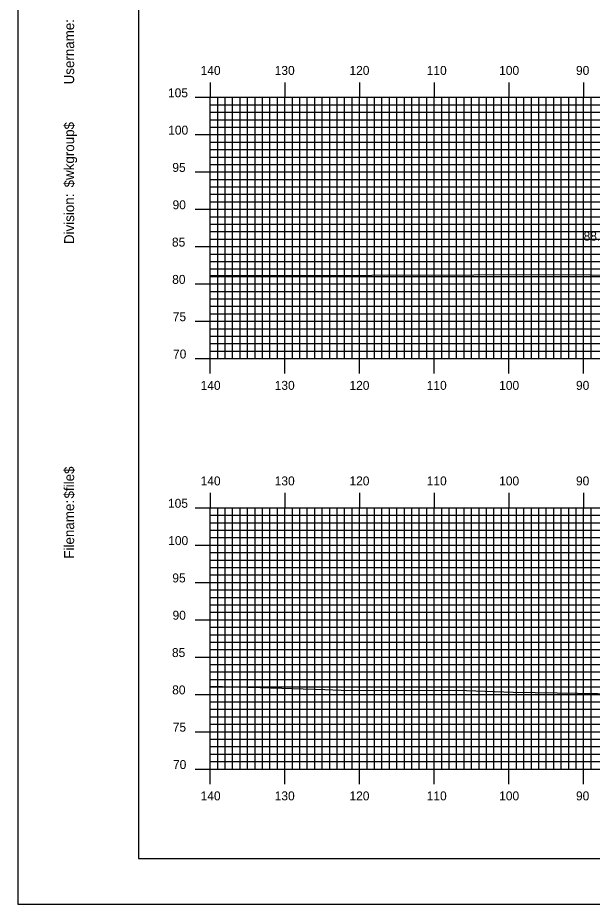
# Model space of a CAD drawing. Extents: x 1756675 to 1757019, y 442591 to 442811.
# Drawn here: x 1756675.3 to 1756752.2, y 442590.5 to 442709.3 of the extents above; entities that cross this region are included whole.
import ezdxf

# ---------------------------------------------------------------- set-up
doc = ezdxf.new("R2010")
doc.units = 0
for name, color, linetype in [('BORDER', 7, 'Continuous'), ('D_Text_Standard', 7, 'Continuous'), ('H_V ANNOTATION', 7, 'Continuous'), ('MAJOR', 7, 'Continuous'), ('MINOR', 7, 'Continuous'), ('PLOT BOUNDARY', 7, 'Continuous'), ('S_Roadway_Centerline', 7, 'Continuous')]:
    doc.layers.add(name, color=color, linetype=linetype)

msp = doc.modelspace()

# ---------------------------------------------------------------- linework, layer by layer
at = {"layer": 'BORDER'}
msp.add_lwpolyline([(1756691.48, 442596.67), (1757011.48, 442596.67), (1757011.48, 442806.67), (1756691.48, 442806.67)], close=True, dxfattribs=at)
at = {"layer": 'MAJOR'}
for p, q in [((1756701.08, 442700.67), (1756701.08, 442698.67)), ((1756711.08, 442700.67), (1756711.08, 442698.67)), ((1756721.08, 442700.67), (1756721.08, 442698.67)), ((1756731.08, 442700.67), (1756731.08, 442698.67)), ((1756741.08, 442700.67), (1756741.08, 442698.67)), ((1756751.08, 442700.67), (1756751.08, 442698.67)), ((1756699.08, 442698.67), (1756701.08, 442698.67)), ((1756701.08, 442698.67), (1756981.08, 442698.67)), ((1756701.08, 442663.67), (1756701.08, 442698.67)), ((1756701.08, 442663.67), (1756701.08, 442698.67)), ((1756701.08, 442698.67), (1756981.08, 442698.67)), ((1756711.08, 442663.67), (1756711.08, 442698.67)), ((1756721.08, 442663.67), (1756721.08, 442698.67)), ((1756731.08, 442663.67), (1756731.08, 442698.67)), ((1756741.08, 442663.67), (1756741.08, 442698.67)), ((1756751.08, 442663.67), (1756751.08, 442698.67)), ((1756699.08, 442693.67), (1756701.08, 442693.67)), ((1756701.08, 442693.67), (1756981.08, 442693.67)), ((1756699.08, 442688.67), (1756701.08, 442688.67)), ((1756701.08, 442688.67), (1756981.08, 442688.67)), ((1756699.08, 442683.67), (1756701.08, 442683.67)), ((1756701.08, 442683.67), (1756981.08, 442683.67)), ((1756699.08, 442678.67), (1756701.08, 442678.67)), ((1756701.08, 442678.67), (1756981.08, 442678.67)), ((1756699.08, 442673.67), (1756701.08, 442673.67)), ((1756701.08, 442673.67), (1756981.08, 442673.67)), ((1756699.08, 442668.67), (1756701.08, 442668.67)), ((1756701.08, 442668.67), (1756981.08, 442668.67)), ((1756699.08, 442663.67), (1756701.08, 442663.67)), ((1756701.08, 442663.67), (1756981.08, 442663.67)), ((1756701.08, 442663.67), (1756981.08, 442663.67)), ((1756701.08, 442661.66), (1756701.08, 442663.67)), ((1756711.08, 442661.66), (1756711.08, 442663.67)), ((1756721.08, 442661.66), (1756721.08, 442663.67)), ((1756731.08, 442661.66), (1756731.08, 442663.67)), ((1756741.08, 442661.66), (1756741.08, 442663.67)), ((1756751.08, 442661.66), (1756751.08, 442663.67)), ((1756701.08, 442645.67), (1756701.08, 442643.67)), ((1756711.08, 442645.67), (1756711.08, 442643.67)), ((1756721.08, 442645.67), (1756721.08, 442643.67)), ((1756731.08, 442645.67), (1756731.08, 442643.67)), ((1756741.08, 442645.67), (1756741.08, 442643.67)), ((1756751.08, 442645.67), (1756751.08, 442643.67)), ((1756699.08, 442643.67), (1756701.08, 442643.67)), ((1756701.08, 442643.67), (1756981.08, 442643.67)), ((1756701.08, 442608.67), (1756701.08, 442643.67)), ((1756701.08, 442608.67), (1756701.08, 442643.67)), ((1756701.08, 442643.67), (1756981.08, 442643.67)), ((1756711.08, 442608.67), (1756711.08, 442643.67)), ((1756721.08, 442608.67), (1756721.08, 442643.67)), ((1756731.08, 442608.67), (1756731.08, 442643.67)), ((1756741.08, 442608.67), (1756741.08, 442643.67)), ((1756751.08, 442608.67), (1756751.08, 442643.67)), ((1756699.08, 442638.67), (1756701.08, 442638.67)), ((1756701.08, 442638.67), (1756981.08, 442638.67)), ((1756699.08, 442633.67), (1756701.08, 442633.67)), ((1756701.08, 442633.67), (1756981.08, 442633.67)), ((1756699.08, 442628.67), (1756701.08, 442628.67)), ((1756701.08, 442628.67), (1756981.08, 442628.67)), ((1756699.08, 442623.67), (1756701.08, 442623.67)), ((1756701.08, 442623.67), (1756981.08, 442623.67)), ((1756699.08, 442618.67), (1756701.08, 442618.67)), ((1756701.08, 442618.67), (1756981.08, 442618.67)), ((1756699.08, 442613.67), (1756701.08, 442613.67)), ((1756701.08, 442613.67), (1756981.08, 442613.67)), ((1756699.08, 442608.67), (1756701.08, 442608.67)), ((1756701.08, 442608.67), (1756981.08, 442608.67)), ((1756701.08, 442608.67), (1756981.08, 442608.67)), ((1756701.08, 442606.66), (1756701.08, 442608.67)), ((1756711.08, 442606.66), (1756711.08, 442608.67)), ((1756721.08, 442606.66), (1756721.08, 442608.67)), ((1756731.08, 442606.66), (1756731.08, 442608.67)), ((1756741.08, 442606.66), (1756741.08, 442608.67)), ((1756751.08, 442606.66), (1756751.08, 442608.67))]:
    msp.add_line(p, q, dxfattribs=at)
at = {"layer": 'MINOR'}
for p, q in [((1756702.08, 442663.67), (1756702.08, 442698.67)), ((1756703.08, 442663.67), (1756703.08, 442698.67)), ((1756704.08, 442663.67), (1756704.08, 442698.67)), ((1756705.08, 442663.67), (1756705.08, 442698.67)), ((1756706.08, 442663.67), (1756706.08, 442698.67)), ((1756707.08, 442663.67), (1756707.08, 442698.67)), ((1756708.08, 442663.67), (1756708.08, 442698.67)), ((1756709.08, 442663.67), (1756709.08, 442698.67)), ((1756710.08, 442663.67), (1756710.08, 442698.67)), ((1756712.08, 442663.67), (1756712.08, 442698.67)), ((1756713.08, 442663.67), (1756713.08, 442698.67)), ((1756714.08, 442663.67), (1756714.08, 442698.67)), ((1756715.08, 442663.67), (1756715.08, 442698.67)), ((1756716.08, 442663.67), (1756716.08, 442698.67)), ((1756717.08, 442663.67), (1756717.08, 442698.67)), ((1756718.08, 442663.67), (1756718.08, 442698.67)), ((1756719.08, 442663.67), (1756719.08, 442698.67)), ((1756720.08, 442663.67), (1756720.08, 442698.67)), ((1756722.08, 442663.67), (1756722.08, 442698.67)), ((1756723.08, 442663.67), (1756723.08, 442698.67)), ((1756724.08, 442663.67), (1756724.08, 442698.67)), ((1756725.08, 442663.67), (1756725.08, 442698.67)), ((1756726.08, 442663.67), (1756726.08, 442698.67)), ((1756727.08, 442663.67), (1756727.08, 442698.67)), ((1756728.08, 442663.67), (1756728.08, 442698.67)), ((1756729.08, 442663.67), (1756729.08, 442698.67)), ((1756730.08, 442663.67), (1756730.08, 442698.67)), ((1756732.08, 442663.67), (1756732.08, 442698.67)), ((1756733.08, 442663.67), (1756733.08, 442698.67)), ((1756734.08, 442663.67), (1756734.08, 442698.67)), ((1756735.08, 442663.67), (1756735.08, 442698.67)), ((1756736.08, 442663.67), (1756736.08, 442698.67)), ((1756737.08, 442663.67), (1756737.08, 442698.67)), ((1756738.08, 442663.67), (1756738.08, 442698.67)), ((1756739.08, 442663.67), (1756739.08, 442698.67)), ((1756740.08, 442663.67), (1756740.08, 442698.67)), ((1756742.08, 442663.67), (1756742.08, 442698.67)), ((1756743.08, 442663.67), (1756743.08, 442698.67)), ((1756744.08, 442663.67), (1756744.08, 442698.67)), ((1756745.08, 442663.67), (1756745.08, 442698.67)), ((1756746.08, 442663.67), (1756746.08, 442698.67)), ((1756747.08, 442663.67), (1756747.08, 442698.67)), ((1756748.08, 442663.67), (1756748.08, 442698.67)), ((1756749.08, 442663.67), (1756749.08, 442698.67)), ((1756750.08, 442663.67), (1756750.08, 442698.67)), ((1756752.08, 442663.67), (1756752.08, 442698.67)), ((1756701.08, 442697.67), (1756981.08, 442697.67)), ((1756701.08, 442697.67), (1756703.09, 442697.67)), ((1756701.08, 442696.67), (1756981.08, 442696.67)), ((1756701.08, 442696.67), (1756703.09, 442696.67)), ((1756701.08, 442695.67), (1756981.08, 442695.67)), ((1756701.08, 442695.67), (1756703.09, 442695.67)), ((1756701.08, 442694.67), (1756981.08, 442694.67)), ((1756701.08, 442694.67), (1756703.09, 442694.67)), ((1756701.08, 442692.67), (1756981.08, 442692.67)), ((1756701.08, 442692.67), (1756703.09, 442692.67)), ((1756701.08, 442691.67), (1756981.08, 442691.67)), ((1756701.08, 442691.67), (1756703.09, 442691.67)), ((1756701.08, 442690.67), (1756981.08, 442690.67)), ((1756701.08, 442690.67), (1756703.09, 442690.67)), ((1756701.08, 442689.67), (1756981.08, 442689.67)), ((1756701.08, 442689.67), (1756703.09, 442689.67)), ((1756701.08, 442687.67), (1756981.08, 442687.67)), ((1756701.08, 442687.67), (1756703.09, 442687.67)), ((1756701.08, 442686.67), (1756981.08, 442686.67)), ((1756701.08, 442686.67), (1756703.09, 442686.67)), ((1756701.08, 442685.67), (1756981.08, 442685.67)), ((1756701.08, 442685.67), (1756703.09, 442685.67)), ((1756701.08, 442684.67), (1756981.08, 442684.67)), ((1756701.08, 442684.67), (1756703.09, 442684.67)), ((1756701.08, 442682.67), (1756981.08, 442682.67)), ((1756701.08, 442682.67), (1756703.09, 442682.67)), ((1756701.08, 442681.67), (1756981.08, 442681.67)), ((1756701.08, 442681.67), (1756703.09, 442681.67)), ((1756701.08, 442680.67), (1756981.08, 442680.67)), ((1756701.08, 442680.67), (1756703.09, 442680.67)), ((1756701.08, 442679.67), (1756981.08, 442679.67)), ((1756701.08, 442679.67), (1756703.09, 442679.67)), ((1756701.08, 442677.67), (1756981.08, 442677.67)), ((1756701.08, 442677.67), (1756703.09, 442677.67)), ((1756701.08, 442676.67), (1756981.08, 442676.67)), ((1756701.08, 442676.67), (1756703.09, 442676.67)), ((1756701.08, 442675.67), (1756981.08, 442675.67)), ((1756701.08, 442675.67), (1756703.09, 442675.67)), ((1756701.08, 442674.67), (1756981.08, 442674.67)), ((1756701.08, 442674.67), (1756703.09, 442674.67)), ((1756701.08, 442672.67), (1756981.08, 442672.67)), ((1756701.08, 442672.67), (1756703.09, 442672.67)), ((1756701.08, 442671.67), (1756981.08, 442671.67)), ((1756701.08, 442671.67), (1756703.09, 442671.67)), ((1756701.08, 442670.67), (1756981.08, 442670.67)), ((1756701.08, 442670.67), (1756703.09, 442670.67)), ((1756701.08, 442669.67), (1756981.08, 442669.67)), ((1756701.08, 442669.67), (1756703.09, 442669.67)), ((1756701.08, 442667.67), (1756981.08, 442667.67)), ((1756701.08, 442667.67), (1756703.09, 442667.67)), ((1756701.08, 442666.67), (1756981.08, 442666.67)), ((1756701.08, 442666.67), (1756703.09, 442666.67)), ((1756701.08, 442665.67), (1756981.08, 442665.67)), ((1756701.08, 442665.67), (1756703.09, 442665.67)), ((1756701.08, 442664.67), (1756981.08, 442664.67)), ((1756701.08, 442664.67), (1756703.09, 442664.67)), ((1756702.08, 442608.67), (1756702.08, 442643.67)), ((1756703.08, 442608.67), (1756703.08, 442643.67)), ((1756704.08, 442608.67), (1756704.08, 442643.67)), ((1756705.08, 442608.67), (1756705.08, 442643.67)), ((1756706.08, 442608.67), (1756706.08, 442643.67)), ((1756707.08, 442608.67), (1756707.08, 442643.67)), ((1756708.08, 442608.67), (1756708.08, 442643.67)), ((1756709.08, 442608.67), (1756709.08, 442643.67)), ((1756710.08, 442608.67), (1756710.08, 442643.67)), ((1756712.08, 442608.67), (1756712.08, 442643.67)), ((1756713.08, 442608.67), (1756713.08, 442643.67)), ((1756714.08, 442608.67), (1756714.08, 442643.67)), ((1756715.08, 442608.67), (1756715.08, 442643.67)), ((1756716.08, 442608.67), (1756716.08, 442643.67)), ((1756717.08, 442608.67), (1756717.08, 442643.67)), ((1756718.08, 442608.67), (1756718.08, 442643.67)), ((1756719.08, 442608.67), (1756719.08, 442643.67)), ((1756720.08, 442608.67), (1756720.08, 442643.67)), ((1756722.08, 442608.67), (1756722.08, 442643.67)), ((1756723.08, 442608.67), (1756723.08, 442643.67)), ((1756724.08, 442608.67), (1756724.08, 442643.67)), ((1756725.08, 442608.67), (1756725.08, 442643.67)), ((1756726.08, 442608.67), (1756726.08, 442643.67)), ((1756727.08, 442608.67), (1756727.08, 442643.67)), ((1756728.08, 442608.67), (1756728.08, 442643.67)), ((1756729.08, 442608.67), (1756729.08, 442643.67)), ((1756730.08, 442608.67), (1756730.08, 442643.67)), ((1756732.08, 442608.67), (1756732.08, 442643.67)), ((1756733.08, 442608.67), (1756733.08, 442643.67)), ((1756734.08, 442608.67), (1756734.08, 442643.67)), ((1756735.08, 442608.67), (1756735.08, 442643.67)), ((1756736.08, 442608.67), (1756736.08, 442643.67)), ((1756737.08, 442608.67), (1756737.08, 442643.67)), ((1756738.08, 442608.67), (1756738.08, 442643.67)), ((1756739.08, 442608.67), (1756739.08, 442643.67)), ((1756740.08, 442608.67), (1756740.08, 442643.67)), ((1756742.08, 442608.67), (1756742.08, 442643.67)), ((1756743.08, 442608.67), (1756743.08, 442643.67)), ((1756744.08, 442608.67), (1756744.08, 442643.67)), ((1756745.08, 442608.67), (1756745.08, 442643.67)), ((1756746.08, 442608.67), (1756746.08, 442643.67)), ((1756747.08, 442608.67), (1756747.08, 442643.67)), ((1756748.08, 442608.67), (1756748.08, 442643.67)), ((1756749.08, 442608.67), (1756749.08, 442643.67)), ((1756750.08, 442608.67), (1756750.08, 442643.67)), ((1756752.08, 442608.67), (1756752.08, 442643.67)), ((1756701.08, 442642.67), (1756981.08, 442642.67)), ((1756701.08, 442642.67), (1756703.09, 442642.67)), ((1756701.08, 442641.67), (1756981.08, 442641.67)), ((1756701.08, 442641.67), (1756703.09, 442641.67)), ((1756701.08, 442640.67), (1756981.08, 442640.67)), ((1756701.08, 442640.67), (1756703.09, 442640.67)), ((1756701.08, 442639.67), (1756981.08, 442639.67)), ((1756701.08, 442639.67), (1756703.09, 442639.67)), ((1756701.08, 442637.67), (1756981.08, 442637.67)), ((1756701.08, 442637.67), (1756703.09, 442637.67)), ((1756701.08, 442636.67), (1756981.08, 442636.67)), ((1756701.08, 442636.67), (1756703.09, 442636.67)), ((1756701.08, 442635.67), (1756981.08, 442635.67)), ((1756701.08, 442635.67), (1756703.09, 442635.67)), ((1756701.08, 442634.67), (1756981.08, 442634.67)), ((1756701.08, 442634.67), (1756703.09, 442634.67)), ((1756701.08, 442632.67), (1756981.08, 442632.67)), ((1756701.08, 442632.67), (1756703.09, 442632.67)), ((1756701.08, 442631.67), (1756981.08, 442631.67)), ((1756701.08, 442631.67), (1756703.09, 442631.67)), ((1756701.08, 442630.67), (1756981.08, 442630.67)), ((1756701.08, 442630.67), (1756703.09, 442630.67)), ((1756701.08, 442629.67), (1756981.08, 442629.67)), ((1756701.08, 442629.67), (1756703.09, 442629.67)), ((1756701.08, 442627.67), (1756981.08, 442627.67)), ((1756701.08, 442627.67), (1756703.09, 442627.67)), ((1756701.08, 442626.67), (1756981.08, 442626.67)), ((1756701.08, 442626.67), (1756703.09, 442626.67)), ((1756701.08, 442625.67), (1756981.08, 442625.67)), ((1756701.08, 442625.67), (1756703.09, 442625.67)), ((1756701.08, 442624.67), (1756981.08, 442624.67)), ((1756701.08, 442624.67), (1756703.09, 442624.67)), ((1756701.08, 442622.67), (1756981.08, 442622.67)), ((1756701.08, 442622.67), (1756703.09, 442622.67)), ((1756701.08, 442621.67), (1756981.08, 442621.67)), ((1756701.08, 442621.67), (1756703.09, 442621.67)), ((1756701.08, 442620.67), (1756981.08, 442620.67)), ((1756701.08, 442620.67), (1756703.09, 442620.67)), ((1756701.08, 442619.67), (1756981.08, 442619.67)), ((1756701.08, 442619.67), (1756703.09, 442619.67)), ((1756701.08, 442617.67), (1756981.08, 442617.67)), ((1756701.08, 442617.67), (1756703.09, 442617.67)), ((1756701.08, 442616.67), (1756981.08, 442616.67)), ((1756701.08, 442616.67), (1756703.09, 442616.67)), ((1756701.08, 442615.67), (1756981.08, 442615.67)), ((1756701.08, 442615.67), (1756703.09, 442615.67)), ((1756701.08, 442614.67), (1756981.08, 442614.67)), ((1756701.08, 442614.67), (1756703.09, 442614.67)), ((1756701.08, 442612.67), (1756981.08, 442612.67)), ((1756701.08, 442612.67), (1756703.09, 442612.67)), ((1756701.08, 442611.67), (1756981.08, 442611.67)), ((1756701.08, 442611.67), (1756703.09, 442611.67)), ((1756701.08, 442610.67), (1756981.08, 442610.67)), ((1756701.08, 442610.67), (1756703.09, 442610.67)), ((1756701.08, 442609.67), (1756981.08, 442609.67)), ((1756701.08, 442609.67), (1756703.09, 442609.67))]:
    msp.add_line(p, q, dxfattribs=at)
at = {"layer": 'PLOT BOUNDARY'}
msp.add_lwpolyline([(1756675.3, 442590.55), (1757015.3, 442590.55), (1757015.3, 442810.55), (1756675.3, 442810.55)], close=True, dxfattribs=at)
at = {"layer": 'S_Roadway_Centerline'}
for points in [[(1756701.08, 442674.81), (1756701.68, 442674.81), (1756706.12, 442674.79), (1756709.1, 442674.81), (1756750.01, 442674.91), (1756753.92, 442674.86), (1756780.55, 442674.65), (1756793.34, 442674.46), (1756796.09, 442674.27), (1756805.61, 442673.9), (1756808.09, 442673.88), (1756821.91, 442673.54), (1756842.06, 442673.4), (1756851.64, 442673.44), (1756857.38, 442673.52), (1756881.46, 442674.48), (1756884.01, 442674.46), (1756914.99, 442674.3), (1756935.3, 442674.49), (1756942.87, 442674.67), (1756956.22, 442674.7), (1756981.08, 442675.14)], [(1756701.08, 442619.75), (1756707.76, 442619.61), (1756716.41, 442619.34), (1756718.62, 442619.24), (1756735.39, 442619.17), (1756741.63, 442618.98), (1756747.56, 442618.88), (1756758.43, 442618.71)]]:
    msp.add_lwpolyline(points, dxfattribs=at)

# ---------------------------------------------------------------- texts
at = {"layer": 'BORDER'}
for s, p in [('Username:', (1756682.85, 442700.4)), ('Username:', (1756682.85, 442700.4)), ('$wkgroup$', (1756682.85, 442686.6)), ('$wkgroup$', (1756682.85, 442686.6)), ('Division:', (1756682.85, 442679)), ('Division:', (1756682.85, 442679)), ('$file$', (1756682.85, 442644.92)), ('$file$', (1756682.85, 442644.92)), ('Filename:', (1756682.85, 442636.86)), ('Filename:', (1756682.85, 442636.86))]:
    msp.add_text(s, height=1.339, rotation=90, dxfattribs=at).set_placement(p)
at = {"layer": 'D_Text_Standard'}
msp.add_text("88.7'", height=1.2, dxfattribs=at).set_placement((1756751.08, 442679.46))
at = {"layer": 'H_V ANNOTATION'}
for s, p in [('140', (1756699.79, 442701.67)), ('130', (1756709.71, 442701.67)), ('120', (1756719.72, 442701.67)), ('110', (1756730.07, 442701.67)), ('100', (1756739.77, 442701.67)), ('90', (1756750.06, 442701.67)), ('105', (1756695.42, 442698.67)), ('100', (1756695.45, 442693.67)), ('95', (1756696, 442688.67)), ('90', (1756696.03, 442683.67)), ('85', (1756695.95, 442678.67)), ('80', (1756695.98, 442673.67)), ('75', (1756696.06, 442668.67)), ('70', (1756696.09, 442663.67)), ('140', (1756699.79, 442659.47)), ('130', (1756709.71, 442659.47)), ('120', (1756719.72, 442659.47)), ('110', (1756730.07, 442659.47)), ('100', (1756739.77, 442659.47)), ('90', (1756750.06, 442659.47)), ('140', (1756699.79, 442646.67)), ('130', (1756709.71, 442646.67)), ('120', (1756719.72, 442646.67)), ('110', (1756730.07, 442646.67)), ('100', (1756739.77, 442646.67)), ('90', (1756750.06, 442646.67)), ('105', (1756695.42, 442643.67)), ('100', (1756695.45, 442638.67)), ('95', (1756696, 442633.67)), ('90', (1756696.03, 442628.67)), ('85', (1756695.95, 442623.67)), ('80', (1756695.98, 442618.67)), ('75', (1756696.06, 442613.67)), ('70', (1756696.09, 442608.67)), ('140', (1756699.79, 442604.47)), ('130', (1756709.71, 442604.47)), ('120', (1756719.72, 442604.47)), ('110', (1756730.07, 442604.47)), ('100', (1756739.77, 442604.47)), ('90', (1756750.06, 442604.47))]:
    msp.add_text(s, height=1.2, dxfattribs=at).set_placement(p)
at = {"layer": 'MAJOR'}
for p in [(1756701.07, 442663.67), (1756701.07, 442608.67)]:
    msp.add_text('-', height=0.012, dxfattribs=at).set_placement(p)

doc.saveas('drawing.dxf')
